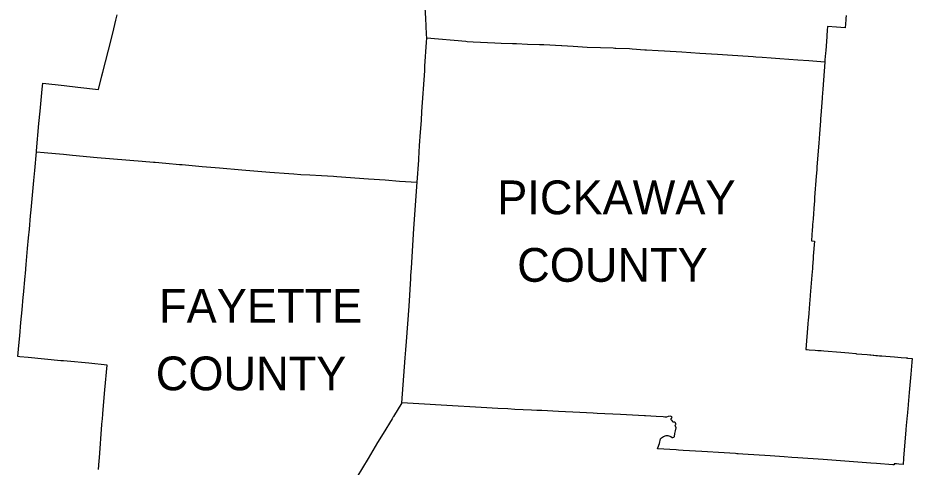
# Model space of a CAD drawing. Extents: x 0 to 34, y 0 to 22.
# Drawn here: x 3.621 to 7.139, y 14.729 to 16.496 of the extents above; entities that cross this region are included whole.
import ezdxf

# ---------------------------------------------------------------- set-up
doc = ezdxf.new("R2010")
doc.units = 0
doc.layers.add('GM_X_County', color=7, linetype='Continuous')
doc.layers.add('SH_Data', color=7, linetype='Continuous')

msp = doc.modelspace()

# ---------------------------------------------------------------- linework, layer by layer
at = {"layer": 'GM_X_County'}
for p, q in [((5.2256, 16.4946), (5.2177, 16.6493)), ((4.0071, 16.4875), (4.0122, 16.5078)), ((6.8795, 16.5053), (6.8785, 16.4932)), ((3.9987, 16.4537), (4.0071, 16.4875)), ((5.2287, 16.4319), (5.2256, 16.4946)), ((6.8783, 16.4889), (6.8755, 16.4574)), ((6.8785, 16.4932), (6.8783, 16.4889)), ((3.9875, 16.4095), (3.9987, 16.4537)), ((5.2301, 16.4165), (5.2287, 16.4319)), ((6.8051, 16.4468), (6.8036, 16.4271)), ((6.8063, 16.4627), (6.8051, 16.4468)), ((6.8414, 16.4601), (6.8063, 16.4627)), ((6.8755, 16.4574), (6.8414, 16.4601)), ((3.9555, 16.2827), (3.9875, 16.4095)), ((5.2227, 16.3063), (5.2291, 16.4011)), ((5.2291, 16.4011), (5.2301, 16.4165)), ((5.3837, 16.4027), (5.2301, 16.4165)), ((5.3891, 16.4023), (5.3837, 16.4027)), ((5.4127, 16.4008), (5.3891, 16.4023)), ((5.4978, 16.3961), (5.4127, 16.4008)), ((5.522, 16.3953), (5.4978, 16.3961)), ((5.5671, 16.3939), (5.522, 16.3953)), ((6.8032, 16.4221), (6.7991, 16.3682)), ((6.8036, 16.4271), (6.8032, 16.4221)), ((5.5823, 16.3936), (5.5671, 16.3939)), ((5.6263, 16.3921), (5.5823, 16.3936)), ((5.6731, 16.3906), (5.6263, 16.3921)), ((5.6902, 16.3901), (5.6731, 16.3906)), ((5.7592, 16.3864), (5.6902, 16.3901)), ((5.7614, 16.3863), (5.7592, 16.3864)), ((5.8059, 16.3835), (5.7614, 16.3863)), ((5.8606, 16.3799), (5.8059, 16.3835)), ((5.9138, 16.378), (5.8606, 16.3799)), ((5.9626, 16.3766), (5.9138, 16.378)), ((5.9698, 16.3763), (5.9626, 16.3766)), ((5.9738, 16.3762), (5.9698, 16.3763)), ((6.0271, 16.3739), (5.9738, 16.3762)), ((6.0378, 16.3732), (6.0271, 16.3739)), ((6.088, 16.3697), (6.0378, 16.3732)), ((6.0941, 16.3693), (6.088, 16.3697)), ((6.1395, 16.3664), (6.0941, 16.3693)), ((6.1652, 16.3653), (6.1395, 16.3664)), ((6.233, 16.3607), (6.1652, 16.3653)), ((6.3043, 16.3563), (6.233, 16.3607)), ((6.7991, 16.3682), (6.7983, 16.3574)), ((6.3734, 16.3525), (6.3043, 16.3563)), ((6.4123, 16.3493), (6.3734, 16.3525)), ((6.5136, 16.3425), (6.4123, 16.3493)), ((6.5245, 16.3418), (6.5136, 16.3425)), ((6.5491, 16.3399), (6.5245, 16.3418)), ((6.5841, 16.3375), (6.5491, 16.3399)), ((6.6194, 16.335), (6.5841, 16.3375)), ((6.6895, 16.3299), (6.6194, 16.335)), ((6.7335, 16.3266), (6.6895, 16.3299)), ((6.7955, 16.3216), (6.7335, 16.3266)), ((6.7963, 16.3316), (6.7955, 16.3216)), ((6.7983, 16.3574), (6.7963, 16.3316)), ((5.2216, 16.2884), (5.2227, 16.3063)), ((6.7955, 16.3216), (6.7903, 16.2513)), ((3.9383, 16.2148), (3.9517, 16.268)), ((3.9517, 16.268), (3.9555, 16.2827)), ((5.2109, 16.1281), (5.2216, 16.2884)), ((3.7164, 16.2163), (3.719, 16.2399)), ((3.719, 16.2399), (3.8038, 16.2301)), ((3.8038, 16.2301), (3.8566, 16.2241)), ((3.8566, 16.2241), (3.9383, 16.2148)), ((6.7903, 16.2513), (6.7876, 16.2159)), ((3.7086, 16.1297), (3.7164, 16.2163)), ((6.7852, 16.1842), (6.785, 16.1807)), ((6.7876, 16.2159), (6.7852, 16.1842)), ((6.785, 16.1807), (6.7798, 16.1117)), ((3.7041, 16.0807), (3.7086, 16.1297)), ((5.2085, 16.0924), (5.2109, 16.1281)), ((3.6943, 15.9728), (3.7041, 16.0807)), ((5.2049, 16.0464), (5.2085, 16.0924)), ((6.7783, 16.0912), (6.7756, 16.0572)), ((6.7788, 16.0999), (6.7783, 16.0912)), ((6.7792, 16.1036), (6.7788, 16.0999)), ((6.7797, 16.1095), (6.7792, 16.1036)), ((6.7798, 16.1117), (6.7797, 16.1095)), ((5.2016, 15.9938), (5.2049, 16.0464)), ((6.7756, 16.0572), (6.7746, 16.0395)), ((6.7746, 16.0395), (6.7716, 16.0032)), ((3.694, 15.9692), (3.6943, 15.9728)), ((5.1982, 15.9418), (5.2016, 15.9938)), ((6.7694, 15.9729), (6.7645, 15.9087)), ((6.7716, 16.0032), (6.7694, 15.9729)), ((3.6873, 15.8955), (3.694, 15.9692)), ((3.694, 15.9692), (3.7239, 15.9666)), ((3.7239, 15.9666), (3.7691, 15.9626)), ((3.7691, 15.9626), (3.8007, 15.9599)), ((3.8007, 15.9599), (3.8362, 15.9566)), ((3.8362, 15.9566), (3.9326, 15.9476)), ((3.9326, 15.9476), (4.1099, 15.9326)), ((5.1979, 15.9366), (5.1982, 15.9418)), ((4.1099, 15.9326), (4.1546, 15.9286)), ((4.1546, 15.9286), (4.161, 15.9281)), ((4.161, 15.9281), (4.2034, 15.9244)), ((4.2034, 15.9244), (4.2566, 15.9197)), ((4.2566, 15.9197), (4.2677, 15.9188)), ((4.2677, 15.9188), (4.3465, 15.9122)), ((4.3465, 15.9122), (4.4139, 15.9065)), ((4.4139, 15.9065), (4.5025, 15.8991)), ((5.1924, 15.8505), (5.1979, 15.9366)), ((6.7645, 15.9081), (6.7637, 15.8983)), ((6.7645, 15.9087), (6.7645, 15.9081)), ((3.6838, 15.8571), (3.6873, 15.8955)), ((4.5025, 15.8991), (4.6127, 15.8898)), ((4.6127, 15.8898), (4.6869, 15.8837)), ((4.6869, 15.8837), (4.7064, 15.8821)), ((4.7064, 15.8821), (4.7348, 15.8803)), ((4.7348, 15.8803), (4.7697, 15.8783)), ((4.7697, 15.8783), (4.8152, 15.8758)), ((4.8152, 15.8758), (4.8632, 15.8735)), ((4.8632, 15.8735), (4.8765, 15.8725)), ((4.8765, 15.8725), (5.0002, 15.8634)), ((6.7619, 15.8742), (6.7555, 15.7896)), ((6.7637, 15.8983), (6.7619, 15.8742)), ((3.6734, 15.7413), (3.6838, 15.8571)), ((5.0002, 15.8634), (5.0666, 15.8585)), ((5.0666, 15.8585), (5.1227, 15.8544)), ((5.1227, 15.8544), (5.1923, 15.8494)), ((5.1791, 15.6682), (5.1923, 15.8494)), ((5.1923, 15.8494), (5.1924, 15.8505)), ((6.7545, 15.7769), (6.7523, 15.7472)), ((6.7555, 15.7896), (6.7545, 15.7769)), ((3.6712, 15.718), (3.6734, 15.7413)), ((6.7523, 15.7472), (6.7506, 15.7247)), ((3.6665, 15.665), (3.6712, 15.718)), ((6.7482, 15.691), (6.7479, 15.6866)), ((6.7493, 15.7073), (6.7482, 15.691)), ((6.7506, 15.7247), (6.7493, 15.7073)), ((3.6634, 15.6315), (3.6665, 15.665)), ((5.1694, 15.5111), (5.1791, 15.6682)), ((6.7461, 15.6595), (6.745, 15.6443)), ((6.7472, 15.6764), (6.7461, 15.6595)), ((6.7479, 15.6866), (6.7472, 15.6764)), ((3.6596, 15.5887), (3.6634, 15.6315)), ((6.745, 15.6425), (6.743, 15.6186)), ((6.745, 15.6443), (6.7449, 15.6434)), ((6.7449, 15.6434), (6.745, 15.6425)), ((3.6539, 15.5262), (3.6596, 15.5887)), ((6.743, 15.6186), (6.7552, 15.6177)), ((6.7552, 15.6177), (6.7505, 15.559)), ((6.7499, 15.5503), (6.7485, 15.5322)), ((6.7505, 15.559), (6.7499, 15.5503)), ((3.6507, 15.4913), (3.6539, 15.5262)), ((6.7478, 15.524), (6.7471, 15.5133)), ((6.748, 15.5267), (6.7478, 15.524)), ((6.7484, 15.5318), (6.748, 15.5267)), ((6.7485, 15.5322), (6.7484, 15.5318)), ((3.6431, 15.4068), (3.6497, 15.4801)), ((3.6497, 15.4801), (3.6507, 15.4913)), ((5.1669, 15.4705), (5.1676, 15.4827)), ((5.1676, 15.4827), (5.1694, 15.5111)), ((6.7447, 15.4844), (6.7435, 15.4682)), ((6.7468, 15.5102), (6.7447, 15.4844)), ((6.7469, 15.5116), (6.7468, 15.5102)), ((6.7471, 15.5133), (6.7469, 15.5116)), ((5.1602, 15.3621), (5.1669, 15.4705)), ((6.7435, 15.4682), (6.7384, 15.4052)), ((3.6377, 15.3484), (3.6423, 15.3977)), ((3.6423, 15.3977), (3.6431, 15.4068)), ((6.7382, 15.4035), (6.7356, 15.3714)), ((6.7383, 15.4048), (6.7382, 15.4035)), ((6.7384, 15.4052), (6.7383, 15.4048)), ((3.6332, 15.2979), (3.6377, 15.3484)), ((5.1499, 15.2236), (5.1602, 15.3621)), ((6.7341, 15.3529), (6.7327, 15.3345)), ((6.7356, 15.3714), (6.7341, 15.3529)), ((6.7306, 15.3086), (6.7292, 15.2922)), ((6.7313, 15.318), (6.7306, 15.3086)), ((6.7327, 15.3345), (6.7313, 15.318)), ((3.6285, 15.2451), (3.6332, 15.2979)), ((6.7292, 15.2922), (6.7212, 15.192)), ((3.6251, 15.2076), (3.6285, 15.2451)), ((3.6211, 15.1638), (3.6251, 15.2076)), ((5.1475, 15.1905), (5.1499, 15.2236)), ((3.6289, 15.1631), (3.6211, 15.1638)), ((3.6619, 15.1599), (3.6289, 15.1631)), ((5.1453, 15.1594), (5.1475, 15.19)), ((5.1475, 15.1901), (5.1475, 15.1905)), ((5.1475, 15.19), (5.1475, 15.1901)), ((6.7212, 15.192), (6.7265, 15.1916)), ((6.7265, 15.1916), (6.7346, 15.191)), ((6.7346, 15.191), (6.7578, 15.1892)), ((6.7578, 15.1892), (6.7679, 15.1884)), ((6.7679, 15.1884), (6.7816, 15.1875)), ((6.7816, 15.1875), (6.7915, 15.1867)), ((6.7915, 15.1867), (6.859, 15.1811)), ((6.859, 15.1811), (6.8907, 15.1781)), ((6.8907, 15.1781), (6.9184, 15.1756)), ((6.9184, 15.1756), (6.9203, 15.1753)), ((6.9203, 15.1753), (6.9628, 15.1715)), ((6.9628, 15.1715), (6.9733, 15.1705)), ((6.9733, 15.1705), (6.9763, 15.1703)), ((6.9763, 15.1703), (6.9864, 15.1694)), ((6.9864, 15.1694), (6.9888, 15.1692)), ((6.9888, 15.1692), (6.9961, 15.1686)), ((6.9961, 15.1686), (7.003, 15.1678)), ((7.003, 15.1678), (7.0108, 15.1672)), ((7.0108, 15.1672), (7.0195, 15.1664)), ((7.0195, 15.1664), (7.0361, 15.1651)), ((7.0361, 15.1651), (7.0701, 15.1623)), ((3.7904, 15.1478), (3.6619, 15.1599)), ((3.8005, 15.1468), (3.7904, 15.1478)), ((3.8435, 15.1428), (3.8005, 15.1468)), ((3.8716, 15.1402), (3.8435, 15.1428)), ((3.8996, 15.1375), (3.8716, 15.1402)), ((3.9719, 15.1307), (3.8996, 15.1375)), ((3.9634, 15.0331), (3.9719, 15.1307)), ((5.1311, 14.9817), (5.1453, 15.1594)), ((7.0701, 15.1623), (7.0956, 15.16)), ((7.0956, 15.16), (7.116, 15.1585)), ((7.116, 15.1585), (7.1185, 15.1588)), ((7.1185, 15.1588), (7.1197, 15.1588)), ((7.1197, 15.1588), (7.1214, 15.1583)), ((7.1214, 15.1583), (7.1223, 15.1579)), ((7.1223, 15.1579), (7.1392, 15.1562)), ((7.1379, 15.1415), (7.1338, 15.0951)), ((7.1392, 15.1562), (7.1379, 15.1415)), ((7.1338, 15.0951), (7.1274, 15.0229)), ((3.9554, 14.9406), (3.9634, 15.0331)), ((7.1274, 15.0229), (7.1232, 14.9752)), ((5.1311, 14.9817), (5.0986, 14.9284)), ((5.1989, 14.978), (5.1311, 14.9817)), ((5.3086, 14.9713), (5.1989, 14.978)), ((5.444, 14.9631), (5.3086, 14.9713)), ((5.5097, 14.9598), (5.444, 14.9631)), ((5.5481, 14.9578), (5.5097, 14.9598)), ((5.5758, 14.9564), (5.5481, 14.9578)), ((5.6412, 14.9532), (5.5758, 14.9564)), ((5.663, 14.9521), (5.6412, 14.9532)), ((5.6824, 14.9512), (5.663, 14.9521)), ((7.1218, 14.9567), (7.1207, 14.9462)), ((7.1232, 14.9752), (7.1218, 14.9567)), ((3.9531, 14.9108), (3.9535, 14.9166)), ((3.9535, 14.9166), (3.9554, 14.9406)), ((5.0931, 14.9194), (5.0577, 14.8611)), ((5.0981, 14.9275), (5.0931, 14.9194)), ((5.0986, 14.9284), (5.0981, 14.9275)), ((5.7479, 14.9483), (5.6824, 14.9512)), ((5.8316, 14.9441), (5.7479, 14.9483)), ((5.8839, 14.9414), (5.8316, 14.9441)), ((5.9001, 14.9406), (5.8839, 14.9414)), ((5.9007, 14.9406), (5.9001, 14.9406)), ((5.9918, 14.9358), (5.9007, 14.9406)), ((6.0864, 14.9311), (5.9918, 14.9358)), ((6.0897, 14.9309), (6.0864, 14.9311)), ((6.1316, 14.9285), (6.0897, 14.9309)), ((6.1603, 14.9272), (6.1316, 14.9285)), ((6.1658, 14.9257), (6.1603, 14.9272)), ((6.173, 14.9262), (6.1658, 14.9257)), ((6.1801, 14.9287), (6.173, 14.9262)), ((6.1872, 14.9295), (6.1801, 14.9287)), ((6.1915, 14.9286), (6.1872, 14.9295)), ((6.1943, 14.9266), (6.1915, 14.9286)), ((6.1915, 14.9156), (6.1919, 14.9184)), ((6.1919, 14.9184), (6.1947, 14.9238)), ((6.1947, 14.9238), (6.1943, 14.9266)), ((7.1185, 14.9188), (7.1161, 14.8926)), ((7.1196, 14.9327), (7.1185, 14.9188)), ((7.1204, 14.943), (7.1196, 14.9327)), ((7.1207, 14.9462), (7.1204, 14.943)), ((3.9417, 14.765), (3.9519, 14.8961)), ((3.9519, 14.8961), (3.953, 14.9099)), ((3.953, 14.9099), (3.9531, 14.9108)), ((6.1924, 14.9141), (6.1915, 14.9156)), ((6.1952, 14.912), (6.1924, 14.9141)), ((6.1974, 14.9065), (6.1952, 14.912)), ((6.1988, 14.9055), (6.1974, 14.9065)), ((6.2057, 14.9054), (6.1988, 14.9055)), ((6.2084, 14.9038), (6.2057, 14.9054)), ((6.2075, 14.8926), (6.2081, 14.8954)), ((6.2107, 14.884), (6.2075, 14.8926)), ((6.2081, 14.8954), (6.2095, 14.8968)), ((6.2102, 14.8995), (6.2084, 14.9038)), ((6.2089, 14.8717), (6.2107, 14.884)), ((6.2095, 14.8968), (6.2102, 14.8995)), ((7.1161, 14.8926), (7.1148, 14.877)), ((5.0577, 14.8611), (5.0363, 14.8257)), ((6.1528, 14.8443), (6.1616, 14.8498)), ((6.1616, 14.8498), (6.1718, 14.8537)), ((6.1718, 14.8537), (6.1777, 14.8535)), ((6.1777, 14.8535), (6.1895, 14.85)), ((6.1895, 14.85), (6.1951, 14.8459)), ((6.1979, 14.8453), (6.2021, 14.8465)), ((6.2021, 14.8465), (6.2048, 14.849)), ((6.2048, 14.849), (6.2062, 14.8616)), ((6.2062, 14.8616), (6.2089, 14.8717)), ((7.1148, 14.8764), (7.1052, 14.7643)), ((7.1148, 14.877), (7.1148, 14.8764)), ((5.0363, 14.8257), (4.9988, 14.7636)), ((6.1389, 14.8048), (6.1455, 14.8225)), ((6.1455, 14.8225), (6.1497, 14.8399)), ((6.1497, 14.8399), (6.1528, 14.8443)), ((6.1951, 14.8459), (6.1979, 14.8453)), ((6.1381, 14.8012), (6.1389, 14.8048)), ((6.2115, 14.797), (6.1381, 14.8012)), ((6.2199, 14.7964), (6.2115, 14.797)), ((6.2389, 14.795), (6.2199, 14.7964)), ((6.3123, 14.7906), (6.2389, 14.795)), ((6.3992, 14.7852), (6.3123, 14.7906)), ((6.4447, 14.7823), (6.3992, 14.7852)), ((6.4496, 14.7819), (6.4447, 14.7823)), ((6.4546, 14.7816), (6.4496, 14.7819)), ((6.4738, 14.7804), (6.4546, 14.7816)), ((6.5809, 14.773), (6.4738, 14.7804)), ((3.9382, 14.7199), (3.9409, 14.7543)), ((3.9409, 14.7543), (3.9417, 14.765)), ((4.9988, 14.7636), (4.954, 14.6895)), ((6.5994, 14.7717), (6.5809, 14.773)), ((6.6173, 14.7704), (6.5994, 14.7717)), ((6.6356, 14.769), (6.6173, 14.7704)), ((6.6655, 14.7669), (6.6356, 14.769)), ((6.689, 14.7653), (6.6655, 14.7669)), ((6.7894, 14.7585), (6.689, 14.7653)), ((6.9771, 14.7449), (6.7894, 14.7585)), ((6.999, 14.7433), (6.9771, 14.7449)), ((7.0627, 14.7387), (6.999, 14.7433)), ((7.0687, 14.7424), (7.0685, 14.7384)), ((7.0772, 14.7415), (7.0687, 14.7424)), ((7.0865, 14.7406), (7.0772, 14.7415)), ((7.104, 14.7417), (7.1039, 14.7396)), ((7.1042, 14.7468), (7.104, 14.7417)), ((7.1047, 14.7545), (7.1042, 14.7468)), ((7.105, 14.7601), (7.1047, 14.7545)), ((7.1052, 14.7643), (7.105, 14.7601)), ((7.0634, 14.7386), (7.0627, 14.7387)), ((7.0685, 14.7384), (7.0634, 14.7386)), ((7.1039, 14.7396), (7.0865, 14.7406))]:
    msp.add_line(p, q, dxfattribs=at)

# ---------------------------------------------------------------- texts
at = {"layer": 'SH_Data'}
for s, p in [('PICKAWAY', (5.5069, 15.7237)), ('COUNTY', (5.5854, 15.4581)), ('FAYETTE', (4.1765, 15.297)), ('COUNTY', (4.1635, 15.0313))]:
    msp.add_text(s, height=0.13282, dxfattribs=at).set_placement(p)

doc.saveas('drawing.dxf')
